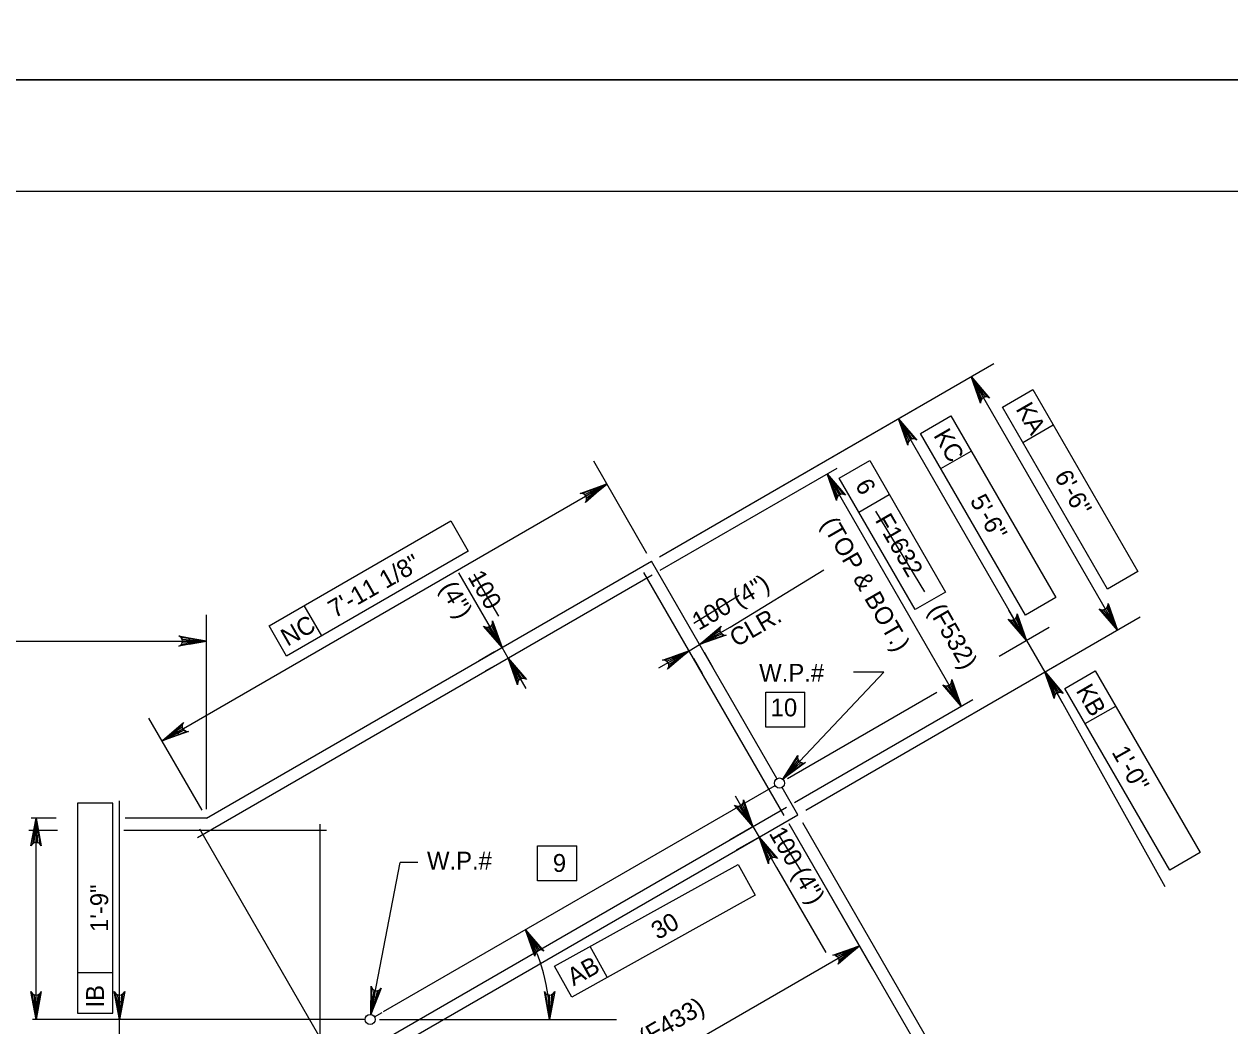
# Model space of a CAD drawing. Extents: x 179 to 454, y -271 to 54.
# Drawn here: x 258.31 to 266.42, y -50.36 to -43.62 of the extents above; entities that cross this region are included whole.
import ezdxf

# ---------------------------------------------------------------- set-up
doc = ezdxf.new("R2010")
doc.units = 0
for name, color, linetype in [('Level 1', 7, 'Continuous'), ('Level 10', 7, 'Continuous'), ('Level 4', 7, 'Continuous'), ('Level 41', 7, 'Continuous'), ('Level 6', 7, 'Continuous'), ('Level 63', 7, 'Continuous')]:
    doc.layers.add(name, color=color, linetype=linetype)

msp = doc.modelspace()

# ---------------------------------------------------------------- linework, layer by layer
at = {"layer": 'Level 1'}
msp.add_lwpolyline([(245.497, -65.25), (276.997, -65.25), (276.997, -44.75), (245.497, -44.75)], close=True, dxfattribs=at)
at = {"layer": 'Level 10'}
for p, q in [((259.5404, -48.966), (262.5337, -47.2379)), ((263.3778, -48.7001), (262.5337, -47.2379)), ((260.7312, -50.2674), (263.3654, -48.7466)), ((263.5179, -48.9427), (263.4118, -48.759)), ((258.5292, -48.966), (258.3607, -48.966)), ((259.5404, -48.966), (258.9928, -48.966)), ((260.3875, -50.75), (263.5179, -48.9427)), ((260.6707, -50.3023), (260.7222, -50.2726)), ((260.6072, -50.3194), (258.3692, -50.3193))]:
    msp.add_line(p, q, dxfattribs=at)
at = {"layer": 'Level 4'}
for p, q in [((262.5869, -47.2071), (264.8377, -45.9076)), ((264.6843, -45.9962), (265.6686, -47.7009)), ((264.8945, -46.2016), (265.0991, -46.0835)), ((265.0991, -46.0835), (265.8051, -47.3063)), ((262.5869, -47.2071), (264.3481, -46.1903)), ((265.6005, -47.4245), (264.8945, -46.2016)), ((264.1947, -46.2789), (264.9968, -47.6683)), ((264.3433, -46.3778), (264.5478, -46.2597)), ((264.5478, -46.2597), (265.2538, -47.4826)), ((265.0314, -46.4387), (265.236, -46.3207)), ((265.0492, -47.6007), (264.3433, -46.3778)), ((263.797, -46.6786), (264.0016, -46.5605)), ((264.0016, -46.5605), (264.5123, -47.4451)), ((264.4802, -46.6149), (264.6848, -46.4968)), ((262.5028, -47.1846), (262.1451, -46.5649)), ((262.5924, -47.2987), (263.7818, -46.6119)), ((259.2404, -48.4464), (262.2336, -46.7182)), ((263.7151, -46.6504), (264.6173, -48.2132)), ((264.3077, -47.5632), (263.797, -46.6786)), ((263.9288, -46.9069), (264.1334, -46.7888)), ((259.9602, -47.6717), (261.183, -46.9657)), ((261.183, -46.9657), (261.3011, -47.1702)), ((261.3011, -47.1702), (260.0782, -47.8762)), ((263.0618, -47.6802), (263.6932, -47.2947)), ((261.4097, -47.614), (261.2376, -47.3158)), ((265.8051, -47.3063), (265.6005, -47.4245)), ((264.5123, -47.4451), (264.3077, -47.5632)), ((260.3154, -47.7393), (260.1973, -47.5347)), ((265.2538, -47.4826), (265.0492, -47.6007)), ((259.5404, -48.9045), (259.5404, -47.5978)), ((261.5279, -47.8186), (261.4097, -47.614)), ((263.5712, -48.9119), (265.822, -47.6123)), ((265.0559, -47.7705), (264.9377, -47.566)), ((260.0782, -47.8762), (259.9602, -47.6717)), ((262.8572, -47.7983), (263.0618, -47.6802)), ((264.8725, -47.8764), (265.2093, -47.682)), ((252.5708, -47.775), (259.5404, -47.775)), ((265.0559, -47.7706), (265.1789, -47.9837)), ((261.4778, -47.8475), (261.3744, -47.9072)), ((261.5689, -47.8896), (261.5279, -47.8186)), ((262.7862, -47.8393), (262.5816, -47.9574)), ((262.7862, -47.8393), (262.8572, -47.7983)), ((262.887, -47.8499), (262.9457, -47.9517)), ((261.5188, -47.9185), (261.4154, -47.9782)), ((261.5689, -47.8896), (261.687, -48.0942)), ((262.816, -47.8909), (262.8748, -47.9928)), ((265.2322, -47.9529), (265.3323, -47.8951)), ((263.4162, -48.7027), (264.0968, -47.985)), ((264.0968, -47.985), (263.893, -47.985)), ((265.182, -47.9819), (265.9867, -49.4257)), ((265.315, -48.0927), (265.5196, -47.9747)), ((265.5196, -47.9747), (266.2256, -49.1975)), ((265.238, -48.0859), (265.297, -48.1882)), ((266.021, -49.3156), (265.315, -48.0927)), ((263.3017, -48.1187), (263.5654, -48.1187)), ((263.3017, -48.3548), (263.3017, -48.1187)), ((263.4481, -48.6988), (264.4543, -48.1179)), ((263.4947, -48.8614), (264.6952, -48.1682)), ((263.5654, -48.3548), (263.5654, -48.1187)), ((265.4519, -48.3298), (265.6565, -48.2117)), ((259.5097, -48.9127), (259.1518, -48.293)), ((263.5654, -48.3548), (263.3017, -48.3548)), ((263.216, -49.0222), (263.0978, -48.8177)), ((258.6723, -48.8657), (258.6723, -50.2778)), ((258.9085, -48.8657), (258.6723, -48.8657)), ((258.9085, -50.2778), (258.9085, -48.8657)), ((258.9544, -50.3193), (258.9544, -48.8487)), ((258.3933, -50.3193), (258.3933, -48.966)), ((263.5487, -48.9959), (265.2809, -51.9962)), ((263.2053, -49.0284), (263.0625, -49.1108)), ((263.216, -49.0222), (263.257, -49.0932)), ((263.4571, -49.0014), (264.3747, -50.5907)), ((263.4571, -49.0014), (264.0212, -49.9784)), ((261.767, -49.1516), (262.0307, -49.1516)), ((261.767, -49.3878), (261.767, -49.1516)), ((262.0307, -49.3878), (262.0307, -49.1516)), ((263.2463, -49.0994), (263.1035, -49.1818)), ((263.2569, -49.0933), (263.3751, -49.2978)), ((266.2256, -49.1975), (266.021, -49.3156)), ((260.6458, -50.286), (260.8435, -49.2652)), ((260.9616, -49.2652), (260.8435, -49.2652)), ((261.8819, -49.9625), (263.1167, -49.2776)), ((263.1167, -49.2776), (263.2313, -49.4842)), ((263.3751, -49.2978), (263.7056, -49.8704)), ((262.0307, -49.3878), (261.767, -49.3878)), ((263.2313, -49.4842), (261.9965, -50.1691)), ((260.9443, -51.5502), (263.9326, -49.825)), ((262.236, -50.0362), (262.1214, -49.8297)), ((261.9965, -50.1691), (261.8819, -49.9625)), ((258.6723, -50.004), (258.9085, -50.004)), ((258.9544, -50.2013), (258.9544, -50.0832)), ((258.6723, -50.2778), (258.9085, -50.2778)), ((258.9544, -50.75), (258.9544, -50.3193)), ((260.7027, -50.3193), (262.2987, -50.3193))]:
    msp.add_line(p, q, dxfattribs=at)
for points in [[(264.7605, -46.0886), (264.7263, -46.1082), (264.6843, -45.9962)], [(264.2707, -46.3713), (264.2367, -46.391), (264.1947, -46.2789)], [(262.1215, -46.7603), (262.1413, -46.7944), (262.2337, -46.7183)], [(263.7912, -46.7429), (263.7572, -46.7626), (263.7151, -46.6504)], [(265.6266, -47.5888), (265.5925, -47.6085), (265.6686, -47.7009)], [(265.0138, -47.6584), (264.9797, -47.6781), (265.0559, -47.7706)], [(259.4223, -47.7553), (259.4223, -47.7947), (259.5404, -47.775)], [(261.4858, -47.7064), (261.4518, -47.7261), (261.5279, -47.8186)], [(262.9497, -47.7222), (262.9693, -47.7563), (262.8572, -47.7983)], [(262.674, -47.8813), (262.6937, -47.9154), (262.7862, -47.8393)], [(261.645, -47.982), (261.6109, -48.0017), (261.5689, -47.8896)], [(265.255, -48.0761), (265.2209, -48.0957), (265.1789, -47.9837)], [(264.5753, -48.101), (264.5412, -48.1208), (264.6173, -48.2132)], [(259.3328, -48.3703), (259.3526, -48.4044), (259.2404, -48.4464)], [(263.5115, -48.6307), (263.483, -48.6037), (263.416, -48.7029)], [(258.4131, -49.0842), (258.3737, -49.0842), (258.3933, -48.966)], [(263.3331, -49.1857), (263.299, -49.2054), (263.257, -49.0932)], [(263.8204, -49.867), (263.8402, -49.9011), (263.9326, -49.8249)], [(258.4131, -50.2013), (258.3737, -50.2013), (258.3933, -50.3193)], [(258.9741, -50.2013), (258.9348, -50.2013), (258.9544, -50.3193)], [(260.6877, -50.1735), (260.649, -50.166), (260.6458, -50.2857)]]:
    msp.add_lwpolyline(points, close=True, dxfattribs=at)
for points in [[(264.6843, -45.9962), (264.8078, -46.1402), (264.792, -46.1327), (264.7775, -46.1325), (264.7656, -46.1369), (264.7558, -46.145), (264.7487, -46.1577), (264.7473, -46.1751), (264.6843, -45.9962), (264.7487, -46.1577), (264.7558, -46.145), (264.6843, -45.9962), (264.7656, -46.1369), (264.7775, -46.1325), (264.6843, -45.9962), (264.792, -46.1327)], [(264.1947, -46.2789), (264.3182, -46.4229), (264.3023, -46.4154), (264.2878, -46.4153), (264.2759, -46.4197), (264.2662, -46.4277), (264.2591, -46.4404), (264.2576, -46.4578), (264.1947, -46.2789), (264.2591, -46.4404), (264.2662, -46.4277), (264.1947, -46.2789), (264.2759, -46.4197), (264.2878, -46.4153), (264.1947, -46.2789), (264.3023, -46.4154)], [(262.2336, -46.7182), (262.0896, -46.8417), (262.0971, -46.8259), (262.0972, -46.8114), (262.0928, -46.7995), (262.0847, -46.7897), (262.0721, -46.7827), (262.0547, -46.7812), (262.2336, -46.7182), (262.0721, -46.7827), (262.0847, -46.7897), (262.2336, -46.7182), (262.0928, -46.7995), (262.0972, -46.8114), (262.2336, -46.7182), (262.0971, -46.8259)], [(263.7151, -46.6504), (263.8386, -46.7944), (263.8227, -46.7869), (263.8082, -46.7867), (263.7963, -46.7912), (263.7866, -46.7993), (263.7794, -46.8119), (263.778, -46.8293), (263.7151, -46.6504), (263.7794, -46.8119), (263.7866, -46.7993), (263.7151, -46.6504), (263.7963, -46.7912), (263.8082, -46.7867), (263.7151, -46.6504), (263.8227, -46.7869)], [(265.6686, -47.7009), (265.5451, -47.5569), (265.5609, -47.5644), (265.5754, -47.5646), (265.5873, -47.5602), (265.5971, -47.5521), (265.6042, -47.5394), (265.6057, -47.522), (265.6686, -47.7009), (265.6042, -47.5394), (265.5971, -47.5521), (265.6686, -47.7009), (265.5873, -47.5602), (265.5754, -47.5646), (265.6686, -47.7009), (265.5609, -47.5644)], [(265.0559, -47.7705), (264.9324, -47.6266), (264.9482, -47.634), (264.9627, -47.6342), (264.9746, -47.6298), (264.9843, -47.6217), (264.9915, -47.609), (264.9929, -47.5916), (265.0559, -47.7705), (264.9915, -47.609), (264.9843, -47.6217), (265.0559, -47.7705), (264.9746, -47.6298), (264.9627, -47.6342), (265.0559, -47.7705), (264.9482, -47.634)], [(261.5279, -47.8186), (261.4044, -47.6747), (261.4203, -47.6821), (261.4348, -47.6822), (261.4467, -47.6778), (261.4564, -47.6698), (261.4635, -47.6571), (261.4649, -47.6397), (261.5279, -47.8186), (261.4635, -47.6571), (261.4564, -47.6698), (261.5279, -47.8186), (261.4467, -47.6778), (261.4348, -47.6822), (261.5279, -47.8186), (261.4203, -47.6821)], [(262.8572, -47.7983), (263.0012, -47.6748), (262.9937, -47.6906), (262.9936, -47.7052), (262.9979, -47.717), (263.0061, -47.7267), (263.0188, -47.7339), (263.0362, -47.7353), (262.8572, -47.7983), (263.0188, -47.7339), (263.0061, -47.7267), (262.8572, -47.7983), (262.9979, -47.717), (262.9936, -47.7052), (262.8572, -47.7983), (262.9937, -47.6906)], [(259.5404, -47.775), (259.354, -47.8099), (259.3683, -47.8), (259.3757, -47.7875), (259.3779, -47.775), (259.3757, -47.7625), (259.3683, -47.75), (259.354, -47.7401), (259.5404, -47.775), (259.3683, -47.75), (259.3757, -47.7625), (259.5404, -47.775), (259.3779, -47.775), (259.3757, -47.7875), (259.5404, -47.775), (259.3683, -47.8)], [(262.7862, -47.8393), (262.6422, -47.9628), (262.6497, -47.947), (262.6498, -47.9325), (262.6454, -47.9206), (262.6373, -47.9108), (262.6247, -47.9037), (262.6072, -47.9022), (262.7862, -47.8393), (262.6247, -47.9037), (262.6373, -47.9108), (262.7862, -47.8393), (262.6454, -47.9206), (262.6498, -47.9325), (262.7862, -47.8393), (262.6497, -47.947)], [(261.5689, -47.8896), (261.6924, -48.0336), (261.6766, -48.0261), (261.6621, -48.0259), (261.6502, -48.0303), (261.6404, -48.0384), (261.6332, -48.0511), (261.6318, -48.0685), (261.5689, -47.8896), (261.6332, -48.0511), (261.6404, -48.0384), (261.5689, -47.8896), (261.6502, -48.0303), (261.6621, -48.0259), (261.5689, -47.8896), (261.6766, -48.0261)], [(265.182, -47.9819), (265.3032, -48.1277), (265.2876, -48.12), (265.2731, -48.1197), (265.2611, -48.1238), (265.2512, -48.1318), (265.2439, -48.1443), (265.2423, -48.1617), (265.182, -47.9819), (265.2439, -48.1443), (265.2512, -48.1318), (265.182, -47.9819), (265.2611, -48.1238), (265.2731, -48.1197), (265.182, -47.9819), (265.2876, -48.12)], [(264.6173, -48.2132), (264.4938, -48.0692), (264.5097, -48.0767), (264.5242, -48.0768), (264.5361, -48.0724), (264.5458, -48.0643), (264.553, -48.0517), (264.5544, -48.0343), (264.6173, -48.2132), (264.553, -48.0517), (264.5458, -48.0643), (264.6173, -48.2132), (264.5361, -48.0724), (264.5242, -48.0768), (264.6173, -48.2132), (264.5097, -48.0767)], [(259.2404, -48.4464), (259.3844, -48.3229), (259.3769, -48.3387), (259.3768, -48.3532), (259.3812, -48.3652), (259.3893, -48.3749), (259.4019, -48.3821), (259.4193, -48.3835), (259.2404, -48.4464), (259.4019, -48.3821), (259.3893, -48.3749), (259.2404, -48.4464), (259.3812, -48.3652), (259.3768, -48.3532), (259.2404, -48.4464), (259.3769, -48.3387)], [(263.4162, -48.7027), (263.5191, -48.5433), (263.5164, -48.5607), (263.5204, -48.5746), (263.528, -48.5847), (263.5385, -48.5918), (263.5527, -48.595), (263.5698, -48.5915), (263.4162, -48.7027), (263.5527, -48.595), (263.5385, -48.5918), (263.4162, -48.7027), (263.528, -48.5847), (263.5204, -48.5746), (263.4162, -48.7027), (263.5164, -48.5607)], [(263.216, -49.0222), (263.0925, -48.8783), (263.1083, -48.8858), (263.1228, -48.8859), (263.1347, -48.8815), (263.1445, -48.8734), (263.1516, -48.8607), (263.153, -48.8433), (263.216, -49.0222), (263.1516, -48.8607), (263.1445, -48.8734), (263.216, -49.0222), (263.1347, -48.8815), (263.1228, -48.8859), (263.216, -49.0222), (263.1083, -48.8858)], [(258.3933, -48.966), (258.4282, -49.1524), (258.4183, -49.1381), (258.4058, -49.1307), (258.3933, -49.1285), (258.3808, -49.1307), (258.3683, -49.1381), (258.3584, -49.1524), (258.3933, -48.966), (258.3683, -49.1381), (258.3808, -49.1307), (258.3933, -48.966), (258.3933, -49.1285), (258.4058, -49.1307), (258.3933, -48.966), (258.4183, -49.1381)], [(263.2569, -49.0933), (263.3804, -49.2372), (263.3647, -49.2298), (263.3501, -49.2297), (263.3383, -49.234), (263.3285, -49.2422), (263.3213, -49.2548), (263.3199, -49.2722), (263.2569, -49.0933), (263.3213, -49.2548), (263.3285, -49.2422), (263.2569, -49.0933), (263.3383, -49.234), (263.3501, -49.2297), (263.2569, -49.0933), (263.3647, -49.2298)], [(261.6864, -49.7159), (261.8099, -49.8599), (261.7941, -49.8524), (261.7796, -49.8522), (261.7677, -49.8567), (261.7579, -49.8648), (261.7508, -49.8774), (261.7493, -49.8948), (261.6864, -49.7159), (261.7508, -49.8774), (261.7579, -49.8648), (261.6864, -49.7159), (261.7677, -49.8567), (261.7796, -49.8522), (261.6864, -49.7159), (261.7941, -49.8524)], [(263.9326, -49.825), (263.7886, -49.9485), (263.7961, -49.9327), (263.7962, -49.9182), (263.7918, -49.9062), (263.7837, -49.8965), (263.7711, -49.8893), (263.7537, -49.8879), (263.9326, -49.825), (263.7711, -49.8893), (263.7837, -49.8965), (263.9326, -49.825), (263.7918, -49.9062), (263.7962, -49.9182), (263.9326, -49.825), (263.7961, -49.9327)], [(258.3933, -50.3193), (258.3584, -50.1329), (258.3683, -50.1472), (258.3808, -50.1547), (258.3933, -50.1568), (258.4058, -50.1547), (258.4183, -50.1472), (258.4282, -50.1329), (258.3933, -50.3193), (258.4183, -50.1472), (258.4058, -50.1547), (258.3933, -50.3193), (258.3933, -50.1568), (258.3808, -50.1547), (258.3933, -50.3193), (258.3683, -50.1472)], [(258.9544, -50.3193), (258.9195, -50.1329), (258.9294, -50.1472), (258.9419, -50.1547), (258.9544, -50.1568), (258.9669, -50.1547), (258.9794, -50.1472), (258.9893, -50.1329), (258.9544, -50.3193), (258.9794, -50.1472), (258.9669, -50.1547), (258.9544, -50.3193), (258.9544, -50.1568), (258.9419, -50.1547), (258.9544, -50.3193), (258.9294, -50.1472)], [(260.6458, -50.286), (260.6469, -50.0963), (260.654, -50.1123), (260.6648, -50.122), (260.6767, -50.1265), (260.6894, -50.1268), (260.7031, -50.1218), (260.7156, -50.1097), (260.6458, -50.286), (260.7031, -50.1218), (260.6894, -50.1268), (260.6458, -50.286), (260.6767, -50.1265), (260.6648, -50.122), (260.6458, -50.286), (260.654, -50.1123)], [(261.8481, -50.3193), (261.8132, -50.1329), (261.8231, -50.1472), (261.8356, -50.1547), (261.8481, -50.1568), (261.8606, -50.1547), (261.8731, -50.1472), (261.8831, -50.1329), (261.8481, -50.3193), (261.8731, -50.1472), (261.8606, -50.1547), (261.8481, -50.3193), (261.8481, -50.1568), (261.8356, -50.1547), (261.8481, -50.3193), (261.8231, -50.1472)]]:
    msp.add_lwpolyline(points, dxfattribs=at)
for centre in [(263.3949, -48.7296), (260.6412, -50.3194)]:
    msp.add_circle(centre, 0.034, dxfattribs=at)
msp.add_arc((260.6412, -50.3194), 1.2069, 0.00169, 29.99989, dxfattribs=at)
at = {"layer": 'Level 41'}
for p, q in [((264.0407, -46.9019), (264.3696, -47.4426)), ((261.3389, -47.325), (261.5033, -47.6072)), ((262.819, -47.6542), (263.1244, -47.4661)), ((263.386, -49.0745), (263.5405, -49.3241))]:
    msp.add_line(p, q, dxfattribs=at)
at = {"layer": 'Level 6'}
for p, q in [((259.4797, -49.0957), (262.5391, -47.3294)), ((263.4263, -48.9482), (262.4831, -47.3144)), ((260.382, -50.6584), (263.4413, -48.8922)), ((258.5377, -49.0481), (258.3438, -49.0481)), ((260.3465, -49.0481), (258.9843, -49.0481)), ((260.438, -50.6734), (259.4948, -49.0397)), ((260.3055, -50.709), (260.3055, -49.0071))]:
    msp.add_line(p, q, dxfattribs=at)
at = {"layer": 'Level 63'}
for points in [[(243.747, -44), (277.747, -44), (277.747, -22), (243.747, -22)], [(243.747, -66), (277.747, -66), (277.747, -44), (243.747, -44)]]:
    msp.add_lwpolyline(points, close=True, dxfattribs=at)

# ---------------------------------------------------------------- texts
at = {"layer": 'Level 4'}
for s, rotation, p in [('KA', 300, (264.9812, -46.2132)), ('KC', 300, (264.4277, -46.3907)), ('(TOP & BOT.)', 300, (263.6717, -46.984)), ('F1632', 300, (264.0347, -46.961)), ('100', 300, (261.2937, -47.3417)), ('100 (4")', 30, (262.8512, -47.7064)), ('(4")', 300, (261.1058, -47.4159)), ('(F532)', 300, (264.3925, -47.5664)), ('NC', 30, (260.0847, -47.8138)), ('CLR.', 30, (263.1037, -47.8188)), ('KB', 300, (265.3862, -48.1075)), ('100 (4")', 300, (263.3203, -49.0673)), ('AB', 29.01629, (262.0093, -50.098)), ('IB', 90, (258.8497, -50.2396)), ('(F433)', 30, (262.4932, -50.5053))]:
    msp.add_text(s, height=0.12, rotation=rotation, dxfattribs=at).set_placement(p)
for p in [(263.2581, -48.048), (261.023, -49.3116)]:
    msp.add_text('W.P.#', height=0.12, dxfattribs=at).set_placement(p)
at = {"layer": 'Level 41'}
for s, rotation, p in [('6\'-6"', 299.35378, (265.2403, -46.6651)), ('6', 299.35378, (263.9002, -46.7252)), ('5\'-6"', 299.35378, (264.6726, -46.8297)), ('7\'-11 1/8"', 29.74761, (260.4022, -47.6226)), ('1\'-0"', 299.35378, (265.6268, -48.5214)), ('1\'-9"', 90, (258.878, -49.7314)), ('30', 29.74761, (262.5757, -49.7869))]:
    msp.add_text(s, height=0.12, rotation=rotation, dxfattribs=at).set_placement(p)
for s, p in [('10', (263.3353, -48.2811)), ('9', (261.8697, -49.3272))]:
    msp.add_text(s, height=0.12, dxfattribs=at).set_placement(p)

doc.saveas('drawing.dxf')
